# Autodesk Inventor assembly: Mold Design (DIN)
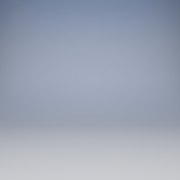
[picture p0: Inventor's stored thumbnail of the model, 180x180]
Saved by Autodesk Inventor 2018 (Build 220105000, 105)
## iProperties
Shininess: 64.0
Length Units: 11269
Angle Units: 11279
Time Units: 11290
Mass Units: 11283
Length Display Precision: 3
Angle Display Precision: 2
Compacted: True
Created: 2002-07
Part Number: Mold Design (DIN)
Document SubType Name: Assembly
Material: Ogólny
Density: 0.0
Volumn: 0.0
Area: 0.0
PropertySet Name: Model Information
Control State: 0
Master: False
Checked Out: False
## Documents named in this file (1)
- C:\Users\Joffi\Desktop\Templates.Base\Metric.Base\Mold Design (DIN).iam
